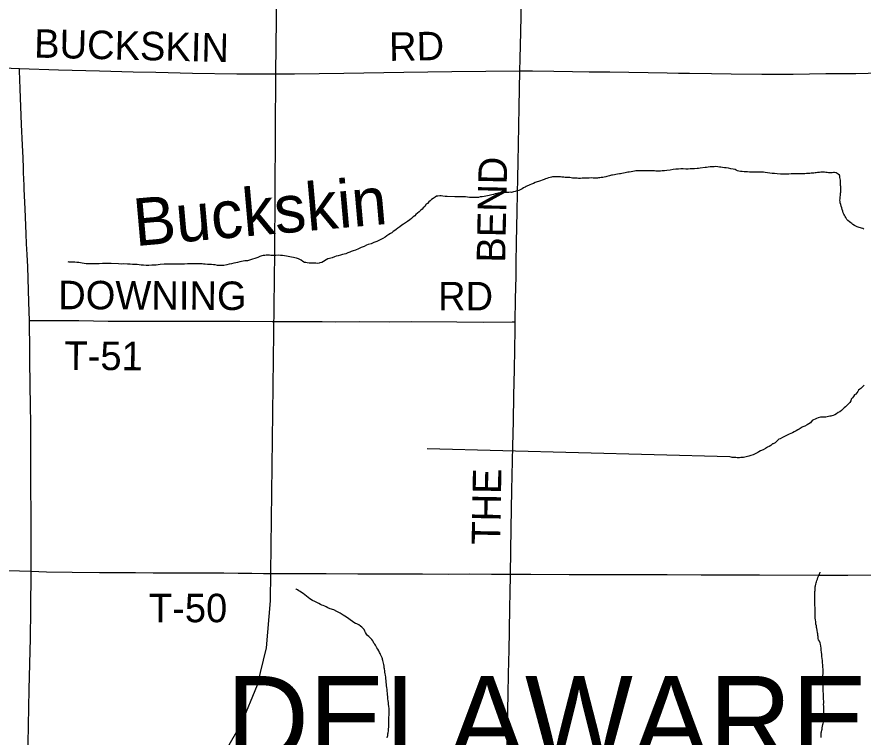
# Model space of a CAD drawing. Extents: x 2.1 to 73.9, y 4 to 26.
# Drawn here: x 44.65 to 45.494, y 23.685 to 24.403 of the extents above; entities that cross this region are included whole.
import ezdxf

# ---------------------------------------------------------------- set-up
doc = ezdxf.new("R2010")
doc.units = 0
for name, color, linetype in [('GM_X_County_Road', 7, 'Continuous'), ('GM_X_County_Road_Text', 7, 'Continuous'), ('GM_X_Minor_River', 7, 'Continuous'), ('GM_X_Minor_River_Text', 7, 'Continuous'), ('GM_X_Rail_Line', 7, 'Continuous'), ('GM_X_Township_Road', 7, 'Continuous'), ('GM_X_Township_Road_Text', 7, 'Continuous'), ('GM_X_Township_Text', 7, 'Continuous')]:
    doc.layers.add(name, color=color, linetype=linetype)

msp = doc.modelspace()

# ---------------------------------------------------------------- linework, layer by layer
at = {"layer": 'GM_X_County_Road'}
for points in [[(45.15193, 24.34944), (45.15216, 24.36148), (45.15276, 24.38821), (45.15376, 24.43545), (45.15451, 24.47771), (45.15565, 24.53366), (45.15644, 24.5697), (45.15687, 24.6007)], [(44.40217, 24.3629), (44.41252, 24.36245), (44.42897, 24.36156), (44.44295, 24.36099), (44.46935, 24.35979), (44.48861, 24.35897), (44.50848, 24.35817), (44.52618, 24.35737), (44.56966, 24.35545), (44.58829, 24.35453), (44.61189, 24.35347), (44.65309, 24.35168)], [(44.65309, 24.35168), (44.69204, 24.35052), (44.73275, 24.34943), (44.76631, 24.34845), (44.78899, 24.34797), (44.82536, 24.34714), (44.86981, 24.3464), (44.92733, 24.34627), (44.97644, 24.34711), (45.03611, 24.34793), (45.08398, 24.34876), (45.15193, 24.34944)], [(45.1473, 24.09916), (45.14768, 24.12186), (45.14815, 24.14455), (45.14842, 24.1576), (45.14876, 24.17811), (45.14941, 24.20919), (45.14972, 24.22722), (45.15002, 24.24244), (45.15032, 24.25861), (45.15058, 24.27601), (45.15128, 24.31331), (45.15193, 24.34944)], [(45.15193, 24.34944), (45.16448, 24.34937), (45.18592, 24.34913), (45.20449, 24.34868), (45.22113, 24.34851), (45.24156, 24.34832), (45.29875, 24.34739), (45.31025, 24.34715), (45.32113, 24.347), (45.34319, 24.34662), (45.36278, 24.34643), (45.39325, 24.34611), (45.42434, 24.34621), (45.45698, 24.34661), (45.48709, 24.34687), (45.51169, 24.34738), (45.54339, 24.34778), (45.56049, 24.34802), (45.57727, 24.34824), (45.59809, 24.34858), (45.61643, 24.34872), (45.6357, 24.34897), (45.64348, 24.34895)], [(45.14253, 23.84741), (45.14333, 23.89343), (45.14405, 23.93135), (45.14492, 23.97517), (45.14547, 24.00003), (45.14597, 24.02582), (45.14648, 24.05162), (45.14717, 24.0914), (45.1473, 24.09916)], [(45.13396, 23.34651), (45.13443, 23.37409), (45.135, 23.41791), (45.13565, 23.46205), (45.13596, 23.48723), (45.13647, 23.52204), (45.13721, 23.56151), (45.13784, 23.59569), (45.13829, 23.62739), (45.13897, 23.66314), (45.13954, 23.69017), (45.14, 23.71255), (45.14029, 23.72747), (45.14061, 23.74829), (45.14116, 23.77198), (45.14159, 23.79024), (45.14203, 23.81542), (45.14219, 23.82785), (45.14253, 23.84741)]]:
    msp.add_lwpolyline(points, dxfattribs=at)
at = {"layer": 'GM_X_Minor_River'}
for points in [[(45.26927, 24.2498), (45.26756, 24.24963), (45.26622, 24.24947), (45.2645, 24.24911), (45.26298, 24.24876), (45.26107, 24.24841), (45.25955, 24.24824), (45.25821, 24.24788), (45.25687, 24.24772), (45.25535, 24.24736), (45.25363, 24.24701), (45.2523, 24.24684), (45.25134, 24.24666), (45.24943, 24.24631), (45.24772, 24.24596), (45.24638, 24.24579), (45.24429, 24.24545), (45.24333, 24.24527), (45.24238, 24.2451), (45.24123, 24.24474), (45.24008, 24.24437), (45.23875, 24.24402), (45.2376, 24.24384), (45.23608, 24.24349), (45.23455, 24.24313), (45.23302, 24.24297), (45.23169, 24.2428), (45.23036, 24.24263), (45.2294, 24.24245), (45.22845, 24.24247), (45.22636, 24.2425), (45.22503, 24.24252), (45.22332, 24.24255), (45.22103, 24.2424), (45.21856, 24.24225), (45.21571, 24.24229), (45.21399, 24.24232), (45.21228, 24.24216), (45.21057, 24.24219), (45.20924, 24.2424), (45.20753, 24.24242), (45.20563, 24.24245), (45.2043, 24.24247), (45.20316, 24.24268), (45.20183, 24.24289), (45.20069, 24.24291), (45.19917, 24.24313), (45.19803, 24.24314), (45.19708, 24.24316), (45.19594, 24.24337), (45.1948, 24.24339), (45.19366, 24.2434), (45.19252, 24.24361), (45.19119, 24.24363), (45.18986, 24.24365), (45.18853, 24.24368), (45.18739, 24.24369), (45.18625, 24.24371), (45.18453, 24.24355), (45.18339, 24.24338), (45.18205, 24.24302), (45.18053, 24.24266), (45.17899, 24.24212), (45.17747, 24.24176), (45.17612, 24.24102), (45.17058, 24.23921), (45.16905, 24.23867), (45.16714, 24.23794), (45.1656, 24.2372), (45.16369, 24.23647), (45.16197, 24.23574), (45.16063, 24.23519), (45.15948, 24.23464), (45.15833, 24.23409), (45.15717, 24.23335), (45.15564, 24.23261), (45.1541, 24.23169), (45.15238, 24.23077), (45.15085, 24.23022), (45.14894, 24.22968), (45.14721, 24.22895), (45.14549, 24.2286), (45.14378, 24.22824), (45.14245, 24.22827), (45.14092, 24.2281), (45.13959, 24.22793), (45.13845, 24.22795), (45.13712, 24.22797), (45.13598, 24.22799), (45.13483, 24.22782), (45.13331, 24.22765), (45.13197, 24.22748), (45.13045, 24.22732), (45.12892, 24.22715), (45.12721, 24.2268), (45.12568, 24.22625), (45.12415, 24.2259), (45.12262, 24.22535), (45.12128, 24.22499), (45.11976, 24.22464), (45.11804, 24.22448)], [(45.46076, 24.2477), (45.45962, 24.24772), (45.45829, 24.24793), (45.45696, 24.24814), (45.45564, 24.24835), (45.45469, 24.24837), (45.45335, 24.24839), (45.45221, 24.24821), (45.45088, 24.24805), (45.44878, 24.24789), (45.44745, 24.24772), (45.44631, 24.24755), (45.44497, 24.24738), (45.44383, 24.2474), (45.4425, 24.24723), (45.44097, 24.24706), (45.43964, 24.2469), (45.43774, 24.24693), (45.43602, 24.24676), (45.43431, 24.24679), (45.43203, 24.24664), (45.42746, 24.24671), (45.42594, 24.24654), (45.42442, 24.24657), (45.42251, 24.2466), (45.42023, 24.24645), (45.41776, 24.24629), (45.41566, 24.24633), (45.41376, 24.24636), (45.41186, 24.24639), (45.40863, 24.24663), (45.40597, 24.24686), (45.4035, 24.24709), (45.40123, 24.24751), (45.39876, 24.24774), (45.39667, 24.24815), (45.39497, 24.24837), (45.39325, 24.24839), (45.39135, 24.24842), (45.38945, 24.24845), (45.38736, 24.24849), (45.38469, 24.24834), (45.3826, 24.24837), (45.38089, 24.2484), (45.37899, 24.24862), (45.37728, 24.24865), (45.37557, 24.24868), (45.37367, 24.2489), (45.37196, 24.24911), (45.37026, 24.24933), (45.36893, 24.24973), (45.36761, 24.25032), (45.36667, 24.25091), (45.36477, 24.25132), (45.36231, 24.25174), (45.35984, 24.25234), (45.35776, 24.25257), (45.35586, 24.25279), (45.35415, 24.25301), (45.35244, 24.25322), (45.35092, 24.25344), (45.34921, 24.25365), (45.34732, 24.25387), (45.3456, 24.25371), (45.3437, 24.25374), (45.3416, 24.25359), (45.33989, 24.25342), (45.33817, 24.25307), (45.33665, 24.2529), (45.33169, 24.25222), (45.33017, 24.25206), (45.32864, 24.25189), (45.32617, 24.25174), (45.32408, 24.25158), (45.32179, 24.25162), (45.3197, 24.25146), (45.31742, 24.2515), (45.31494, 24.25154), (45.31247, 24.25158), (45.31, 24.25143), (45.30752, 24.25128), (45.30485, 24.25094), (45.3018, 24.25042), (45.29838, 24.25009), (45.29609, 24.24975), (45.29399, 24.24959), (45.29209, 24.24943), (45.29037, 24.24927), (45.28905, 24.24948), (45.28753, 24.24951), (45.28619, 24.24953), (45.28467, 24.24955), (45.28315, 24.24977), (45.28163, 24.24979), (45.27973, 24.24963), (45.27688, 24.24968), (45.27498, 24.24971), (45.27345, 24.24973), (45.27174, 24.24976), (45.27041, 24.24978), (45.26927, 24.2498)], [(45.49486, 24.1915), (45.49392, 24.19209), (45.49032, 24.19328), (45.48937, 24.19349), (45.48843, 24.19388), (45.48692, 24.19448), (45.4856, 24.19507), (45.48409, 24.19623), (45.48296, 24.19701), (45.48203, 24.19778), (45.48052, 24.19895), (45.47902, 24.20011), (45.4779, 24.20127), (45.47697, 24.20299), (45.47623, 24.20414), (45.47568, 24.20548), (45.47494, 24.20664), (45.47439, 24.20797), (45.47385, 24.2095), (45.47349, 24.21122), (45.47295, 24.21275), (45.4724, 24.21446), (45.47186, 24.21618), (45.4715, 24.21771), (45.47133, 24.21904), (45.47117, 24.22037), (45.47119, 24.22189), (45.47141, 24.22379), (45.47181, 24.22511), (45.47183, 24.22644), (45.47185, 24.22758), (45.47187, 24.22853), (45.47189, 24.22967), (45.47209, 24.23061), (45.47192, 24.23176), (45.47194, 24.23289), (45.47196, 24.23403), (45.47178, 24.23499), (45.4718, 24.23632), (45.47182, 24.23727), (45.47184, 24.23898), (45.47168, 24.2405), (45.47151, 24.24183), (45.47115, 24.24316), (45.47098, 24.24431), (45.47061, 24.24526), (45.46949, 24.24642), (45.46836, 24.24701), (45.46723, 24.2476), (45.46571, 24.248), (45.46457, 24.24802), (45.46323, 24.24766), (45.4619, 24.24768), (45.46076, 24.2477)], [(45.11804, 24.22448), (45.11632, 24.22393), (45.11423, 24.22378), (45.11251, 24.22361), (45.1106, 24.22326), (45.10832, 24.22311), (45.10623, 24.22314), (45.10375, 24.22299), (45.10166, 24.22322), (45.09976, 24.22344), (45.09768, 24.22385), (45.09559, 24.22388), (45.09331, 24.22392), (45.08988, 24.22378), (45.08703, 24.22383), (45.07961, 24.22395), (45.07733, 24.22417), (45.07525, 24.2244), (45.07354, 24.22461), (45.07221, 24.22483), (45.07011, 24.22448), (45.06897, 24.22431), (45.06743, 24.22338), (45.06647, 24.22283), (45.06551, 24.22208), (45.06397, 24.22097), (45.06243, 24.21985), (45.06127, 24.21873), (45.05992, 24.21723), (45.05857, 24.21631), (45.05721, 24.21424), (45.05566, 24.21274), (45.0545, 24.21162), (45.05315, 24.2105), (45.05141, 24.20882), (45.04814, 24.20622), (45.04717, 24.2049), (45.04544, 24.20379), (45.04389, 24.20229), (45.04216, 24.20099), (45.04004, 24.19932), (45.03792, 24.19783), (45.036, 24.19653), (45.03427, 24.19542), (45.03235, 24.19393), (45.03042, 24.19244), (45.0285, 24.19114), (45.02715, 24.19021), (45.02561, 24.1891), (45.02426, 24.18798), (45.02292, 24.18705), (45.02138, 24.18613), (45.02042, 24.18557), (45.01927, 24.18483), (45.01753, 24.18353), (45.01523, 24.18224), (45.01274, 24.18095), (45.00948, 24.17929), (45.00642, 24.1782), (45.00373, 24.17691), (45.00068, 24.1762), (44.99896, 24.17547), (44.99666, 24.17437), (44.99378, 24.17308), (44.99091, 24.1718), (44.98804, 24.17071), (44.98574, 24.16998), (44.98383, 24.16925), (44.9823, 24.16852), (44.98038, 24.16779), (44.97828, 24.16706), (44.97522, 24.16616), (44.97312, 24.16544), (44.97083, 24.1649), (44.96892, 24.16455), (44.96701, 24.16382), (44.96471, 24.1631), (44.96223, 24.16219), (44.96051, 24.16184), (44.95456, 24.15832), (44.95264, 24.15779), (44.95169, 24.15761), (44.95036, 24.15744), (44.94865, 24.15747), (44.94617, 24.15751), (44.94389, 24.15755), (44.9418, 24.15777), (44.93991, 24.15799), (44.93839, 24.1582), (44.93725, 24.15841), (44.93555, 24.1592), (44.93386, 24.16055), (44.93254, 24.16115), (44.93122, 24.16193), (44.92914, 24.16253), (44.92762, 24.16293), (44.92611, 24.16334), (44.9244, 24.16355), (44.92269, 24.16396), (44.92099, 24.16437), (44.91909, 24.16459)], [(44.91909, 24.16459), (44.91719, 24.165), (44.9153, 24.16522), (44.9132, 24.16525), (44.91131, 24.16547), (44.90864, 24.16533), (44.90674, 24.16536), (44.90522, 24.16538), (44.9037, 24.1654), (44.90237, 24.16562), (44.90084, 24.16545), (44.89913, 24.16548), (44.89761, 24.16531), (44.89608, 24.16515), (44.89456, 24.16479), (44.89265, 24.16425), (44.89073, 24.16333), (44.88767, 24.16243), (44.88519, 24.16152), (44.88232, 24.16062), (44.88022, 24.16008), (44.87908, 24.1601), (44.87774, 24.15993), (44.87278, 24.15887), (44.8703, 24.15834), (44.86858, 24.15799), (44.86667, 24.15764), (44.86457, 24.1571), (44.86209, 24.15657), (44.85961, 24.15604), (44.85675, 24.15533), (44.85408, 24.15518), (44.85237, 24.15521), (44.85142, 24.15522), (44.85047, 24.15543), (44.84801, 24.15585), (44.84649, 24.15606), (44.84459, 24.15628), (44.84269, 24.15631), (44.84041, 24.15635), (44.83813, 24.15657), (44.83642, 24.15679), (44.83528, 24.157), (44.83376, 24.15702), (44.83205, 24.15705), (44.82977, 24.15709), (44.82615, 24.15696), (44.8233, 24.157), (44.82044, 24.15686), (44.81759, 24.15671), (44.81474, 24.15676), (44.81169, 24.15662), (44.80865, 24.15667), (44.80523, 24.15672), (44.80142, 24.15678), (44.79742, 24.15647), (44.79323, 24.15615), (44.78942, 24.15564), (44.78486, 24.15553), (44.782, 24.15538), (44.77934, 24.15542), (44.77668, 24.15566), (44.7744, 24.15569), (44.77231, 24.15592), (44.77022, 24.15614), (44.76813, 24.15636), (44.76566, 24.1564), (44.76338, 24.15663), (44.76072, 24.15667), (44.75711, 24.15692), (44.75425, 24.15678), (44.7516, 24.15701), (44.74456, 24.15731), (44.74266, 24.15734), (44.74057, 24.15737), (44.73829, 24.15741), (44.73562, 24.15726), (44.73239, 24.15712), (44.72915, 24.15699), (44.72478, 24.15687), (44.72192, 24.15691), (44.71945, 24.15695), (44.71736, 24.15718), (44.71566, 24.15758), (44.71376, 24.1578), (44.71205, 24.15821), (44.71016, 24.15843), (44.70825, 24.15846), (44.70636, 24.15868), (44.70445, 24.15871), (44.70255, 24.15874), (44.7016, 24.15895), (44.7016, 24.15876), (44.70141, 24.15876)], [(45.4954, 24.03595), (45.49367, 24.03445), (45.49193, 24.03258), (45.49096, 24.03184), (45.48962, 24.0311), (45.48903, 24.02959), (45.48805, 24.02828), (45.48689, 24.02697), (45.48574, 24.02623), (45.48457, 24.02472), (45.4836, 24.02341), (45.48244, 24.02191), (45.48203, 24.0204), (45.48086, 24.01871), (45.47989, 24.01758), (45.47873, 24.01646), (45.47758, 24.01534), (45.47661, 24.01441), (45.47545, 24.01328), (45.4741, 24.01217), (45.47275, 24.01086), (45.47101, 24.00956), (45.46948, 24.00882), (45.46756, 24.00733), (45.46602, 24.00641), (45.4643, 24.00587), (45.46315, 24.0055), (45.46201, 24.00514), (45.46105, 24.00497), (45.45704, 24.00408), (45.4559, 24.0041), (45.45495, 24.00412), (45.454, 24.00413), (45.45267, 24.00415), (45.45172, 24.00417), (45.44942, 24.00325), (45.44789, 24.00271), (45.44636, 24.00216), (45.44483, 24.00143), (45.4433, 24.00069), (45.44193, 23.99844), (45.43847, 23.99659), (45.43598, 23.99511), (45.43425, 23.99438), (45.4333, 23.99402), (45.43157, 23.9929), (45.43041, 23.99216), (45.42907, 23.99142), (45.42753, 23.9905), (45.42562, 23.98958), (45.4237, 23.98847), (45.42063, 23.987), (45.41852, 23.98609), (45.41641, 23.98498), (45.41373, 23.98369), (45.41162, 23.98259), (45.41028, 23.98204), (45.40893, 23.98092), (45.40777, 23.9798), (45.40642, 23.97849), (45.40469, 23.97757)], [(45.36131, 23.9644), (45.05941, 23.97262)], [(45.40469, 23.97757), (45.40374, 23.97739), (45.40238, 23.9759), (45.40047, 23.97498), (45.39874, 23.97425), (45.39682, 23.97276), (45.39451, 23.97146), (45.39183, 23.97037), (45.3903, 23.96963), (45.38934, 23.96889), (45.38742, 23.96778), (45.38589, 23.96704), (45.38454, 23.9665), (45.38225, 23.96596), (45.38015, 23.96524), (45.37748, 23.96452), (45.3748, 23.96399), (45.37328, 23.96383), (45.37214, 23.96384), (45.371, 23.96367), (45.36985, 23.9635), (45.36852, 23.96352), (45.36719, 23.96373), (45.36586, 23.96375), (45.36453, 23.96397), (45.36358, 23.96398), (45.36264, 23.96419), (45.36131, 23.9644)], [(45.45468, 23.72781), (45.45455, 23.73123), (45.4544, 23.7339), (45.45425, 23.73656), (45.45429, 23.73902), (45.45433, 23.74149), (45.45418, 23.74396), (45.45422, 23.74624), (45.45426, 23.74852), (45.45448, 23.75061), (45.45432, 23.7527), (45.45417, 23.75498), (45.45401, 23.75688), (45.45386, 23.75954), (45.4537, 23.76144), (45.45336, 23.76354), (45.4532, 23.76544), (45.45304, 23.76753), (45.45288, 23.76962), (45.45254, 23.77172), (45.45238, 23.77381), (45.45203, 23.77571), (45.45168, 23.77762), (45.45133, 23.77914), (45.45059, 23.78086), (45.44985, 23.7822), (45.44949, 23.78335), (45.44932, 23.78449), (45.44933, 23.78544), (45.44916, 23.78639), (45.449, 23.7881), (45.44882, 23.78906), (45.44848, 23.79172), (45.44794, 23.79325), (45.44777, 23.79439), (45.4476, 23.79591), (45.44725, 23.79782), (45.4471, 23.8001), (45.44675, 23.802), (45.44659, 23.80371), (45.44643, 23.80562), (45.44645, 23.80733), (45.44648, 23.80884), (45.44651, 23.81093), (45.44635, 23.81264), (45.44638, 23.81454), (45.44621, 23.81606), (45.44605, 23.81778), (45.44607, 23.8191), (45.44609, 23.82024), (45.44612, 23.82176), (45.44595, 23.82309), (45.44597, 23.82442), (45.44618, 23.82575), (45.4462, 23.82689), (45.44622, 23.82822), (45.44624, 23.82917), (45.44625, 23.83031), (45.44627, 23.83125), (45.44628, 23.8322), (45.44631, 23.83391), (45.44652, 23.83505), (45.44673, 23.836), (45.44694, 23.8377), (45.44734, 23.83883), (45.44774, 23.83997), (45.44814, 23.84129), (45.44873, 23.84261), (45.44914, 23.84412), (45.44973, 23.84563), (45.45033, 23.84695), (45.45072, 23.8479), (45.4515, 23.84921), (45.45151, 23.8494)], [(44.9286, 23.83284), (44.92841, 23.83285)], [(45.02135, 23.69919), (45.02137, 23.70033), (45.02139, 23.70128), (45.02122, 23.70242), (45.02142, 23.70336), (45.02144, 23.70431), (45.02145, 23.70526), (45.02148, 23.70678), (45.02149, 23.70792), (45.02152, 23.70925), (45.02173, 23.71077), (45.02175, 23.71172), (45.02176, 23.71266), (45.02159, 23.714), (45.02142, 23.71514), (45.02144, 23.71609), (45.02108, 23.71761), (45.02092, 23.71952), (45.02057, 23.72123), (45.02041, 23.72332), (45.02025, 23.72541), (45.02009, 23.72732), (45.01993, 23.72884), (45.01977, 23.73074), (45.01961, 23.73264), (45.01945, 23.73454), (45.01909, 23.73607), (45.01893, 23.73778), (45.01877, 23.73949), (45.01861, 23.74139), (45.01845, 23.74311), (45.01829, 23.74501), (45.01793, 23.74672), (45.01777, 23.74824), (45.01741, 23.74977), (45.01725, 23.75129), (45.01708, 23.753), (45.01672, 23.75415), (45.01656, 23.75586), (45.01621, 23.75757), (45.01585, 23.75891), (45.01568, 23.76024), (45.01532, 23.76139), (45.01514, 23.76234), (45.01497, 23.76329), (45.0146, 23.76425), (45.01313, 23.76731), (45.01258, 23.76846), (45.01202, 23.7696), (45.01129, 23.77095), (45.01036, 23.77267), (45.00944, 23.7742), (45.0087, 23.77554), (45.00795, 23.7767), (45.0074, 23.77766), (45.00646, 23.77862), (45.00591, 23.77977), (45.00536, 23.78092), (45.00443, 23.78226), (45.00275, 23.784), (45.00125, 23.78535), (44.99993, 23.78651), (44.999, 23.78766), (44.99789, 23.78939), (44.99734, 23.79073), (44.9966, 23.79226), (44.99586, 23.79341), (44.99436, 23.79476), (44.99305, 23.79573), (44.99135, 23.7969), (44.98928, 23.79788), (44.98814, 23.79828), (44.98645, 23.79926), (44.98137, 23.80314), (44.97892, 23.8047), (44.97591, 23.80664), (44.97271, 23.80859), (44.96951, 23.81035), (44.96649, 23.81192), (44.9627, 23.81312), (44.96044, 23.81411), (44.95874, 23.81508), (44.95742, 23.81567), (44.95591, 23.81627), (44.95458, 23.81667), (44.95326, 23.81745), (44.95157, 23.81823), (44.94949, 23.81922), (44.94742, 23.82039), (44.94534, 23.82137), (44.94251, 23.82294), (44.94082, 23.82429), (44.93913, 23.82546), (44.93744, 23.82701), (44.93575, 23.82817), (44.93406, 23.82934), (44.93274, 23.83031), (44.93161, 23.8309), (44.9301, 23.83187), (44.92878, 23.83265), (44.9286, 23.83284)], [(45.45228, 23.68474), (45.4523, 23.68569), (45.45231, 23.68664), (45.45253, 23.68816), (45.45254, 23.6893), (45.45275, 23.69024), (45.45316, 23.69195), (45.45337, 23.69308), (45.45357, 23.69422), (45.4542, 23.69763), (45.45441, 23.69876), (45.45462, 23.70009), (45.45464, 23.70142), (45.45466, 23.70294), (45.45469, 23.70464), (45.45491, 23.70654), (45.45495, 23.70901), (45.45499, 23.7111), (45.45501, 23.71281), (45.45504, 23.71452), (45.45507, 23.71603), (45.4549, 23.71775), (45.45493, 23.71926), (45.45495, 23.72097), (45.4548, 23.72287), (45.45483, 23.72515), (45.45468, 23.72781)], [(45.01959, 23.68421), (45.02, 23.68572), (45.0202, 23.68667), (45.02042, 23.68838), (45.02063, 23.68951), (45.02085, 23.69122), (45.02106, 23.69273), (45.0213, 23.69577), (45.02132, 23.69672), (45.02133, 23.69786), (45.02135, 23.69919)]]:
    msp.add_lwpolyline(points, dxfattribs=at)
at = {"layer": 'GM_X_Rail_Line'}
msp.add_lwpolyline([(44.25279, 22.99625), (44.25498, 23.0348), (44.25803, 23.06783), (44.26715, 23.10087), (44.27758, 23.12043), (44.29583, 23.15563), (44.31538, 23.18258), (44.3471, 23.21431), (44.40098, 23.26169), (44.50613, 23.35296), (44.6569, 23.48292), (44.79159, 23.59898), (44.81114, 23.61506), (44.82896, 23.63201), (44.85329, 23.66244), (44.87458, 23.69938), (44.89022, 23.7372), (44.89935, 23.77414), (44.90326, 23.82108), (44.90369, 23.8489), (44.9076, 24.16793), (44.90847, 24.34745), (44.91499, 24.84946), (44.91547, 24.90511)], dxfattribs=at)
at = {"layer": 'GM_X_Township_Road'}
for points in [[(44.66282, 24.10038), (44.66271, 24.1095), (44.66244, 24.11913), (44.66116, 24.15393), (44.66065, 24.16636), (44.66014, 24.17692), (44.65968, 24.18686), (44.65877, 24.21171), (44.6578, 24.23128), (44.65756, 24.23656), (44.65743, 24.23997), (44.6571, 24.24929), (44.65698, 24.2524), (44.65659, 24.26265), (44.65596, 24.27538), (44.65507, 24.29589), (44.65364, 24.3313), (44.65328, 24.3406), (44.65313, 24.3493), (44.65309, 24.35168)], [(44.66282, 24.10038), (44.66625, 24.10038), (44.68519, 24.10041), (44.69887, 24.10043), (44.71223, 24.10034), (44.74137, 24.09991), (44.77711, 24.09977), (44.80104, 24.09977), (44.8343, 24.09981), (44.87284, 24.09965), (44.90486, 24.09947), (44.95489, 24.0993), (44.96826, 24.09927), (44.9922, 24.09931), (45.02203, 24.09927), (45.04377, 24.09931), (45.08915, 24.09916), (45.11619, 24.09894), (45.14415, 24.09914), (45.1473, 24.09916)], [(44.66479, 23.85046), (44.66476, 23.85746), (44.66452, 23.87331), (44.66455, 23.88482), (44.66464, 23.89072), (44.66464, 23.90503), (44.66437, 23.93705), (44.66434, 23.97405), (44.66437, 23.98182), (44.66444, 23.98368), (44.66436, 23.98523), (44.6642, 24.00388), (44.6641, 24.00977), (44.66402, 24.01381), (44.66375, 24.03806), (44.66372, 24.04178), (44.66366, 24.04238), (44.66357, 24.04422), (44.66332, 24.05261), (44.66317, 24.06971), (44.66282, 24.10038)], [(44.44166, 23.85882), (44.44277, 23.85879), (44.4667, 23.85825), (44.49622, 23.85716), (44.50927, 23.85665), (44.52169, 23.85623), (44.54127, 23.85546), (44.55804, 23.85481), (44.58382, 23.85369), (44.59812, 23.85319), (44.61333, 23.85249), (44.64191, 23.85135), (44.66391, 23.8505), (44.66479, 23.85046)], [(44.656, 23.34725), (44.65624, 23.35612), (44.65714, 23.39614), (44.65755, 23.41758), (44.65839, 23.46389), (44.65872, 23.48813), (44.6593, 23.52107), (44.65947, 23.53972), (44.66017, 23.60685), (44.66257, 23.73239), (44.66386, 23.78366), (44.66436, 23.81163), (44.66479, 23.85046)], [(44.66479, 23.85046), (44.67985, 23.85003), (44.70564, 23.8497), (44.73268, 23.84928), (44.74885, 23.84916), (44.76874, 23.84905), (44.78614, 23.84895), (44.79764, 23.84892), (44.81629, 23.84872), (44.8424, 23.84876), (44.8567, 23.84872), (44.871, 23.84856), (44.88467, 23.84849), (44.89648, 23.84831), (44.90239, 23.84828), (44.90829, 23.84827), (44.91606, 23.84815), (44.94714, 23.84815), (44.95895, 23.84819), (44.99035, 23.84799), (45.01366, 23.84803), (45.03666, 23.84796), (45.055, 23.84779), (45.08111, 23.84768), (45.10194, 23.84772), (45.12369, 23.84758), (45.14253, 23.84741)], [(45.14253, 23.84741), (45.14483, 23.8474), (45.16285, 23.84738), (45.20109, 23.84732), (45.21725, 23.84723), (45.22968, 23.84731), (45.23932, 23.84734), (45.25641, 23.84728), (45.28159, 23.84714), (45.29869, 23.8471), (45.33288, 23.84695), (45.35619, 23.84689), (45.38976, 23.84678), (45.39076, 23.84678)], [(45.39076, 23.84678), (45.44944, 23.84666), (45.46156, 23.84666), (45.47897, 23.84671), (45.52404, 23.84687), (45.53865, 23.84687), (45.55823, 23.8469), (45.57905, 23.84686), (45.5977, 23.84673), (45.61667, 23.84679), (45.63127, 23.8467), (45.63994, 23.84664)]]:
    msp.add_lwpolyline(points, dxfattribs=at)

# ---------------------------------------------------------------- texts
at = {"layer": 'GM_X_County_Road_Text'}
for s, rotation, p in [('BUCKSKIN', 358.66689, (44.66736, 24.36261)), ('RD', 0.98235, (45.02175, 24.35927)), ('BEND', 88.80652, (45.13722, 24.15788)), ('THE', 88.9485, (45.13222, 23.8767))]:
    msp.add_text(s, height=0.028409, rotation=rotation, dxfattribs=at).set_placement(p)
at = {"layer": 'GM_X_Minor_River_Text'}
msp.add_text('Buckskin', height=0.047376, rotation=5.04384, dxfattribs=at).set_placement((44.7685, 24.17454))
at = {"layer": 'GM_X_Township_Road_Text'}
for s, rotation, p in [('DOWNING', 359.72262, (44.69155, 24.11176)), ('RD', 0.00001, (45.07038, 24.11051)), ('T-51', 359.63362, (44.69773, 24.0513)), ('T-50', 0.00001, (44.78204, 23.79961))]:
    msp.add_text(s, height=0.028409, rotation=rotation, dxfattribs=at).set_placement(p)
at = {"layer": 'GM_X_Township_Text'}
msp.add_text('DELAWARE', height=0.085227, rotation=0.00001, dxfattribs=at).set_placement((44.85933, 23.66078))

doc.saveas('drawing.dxf')
